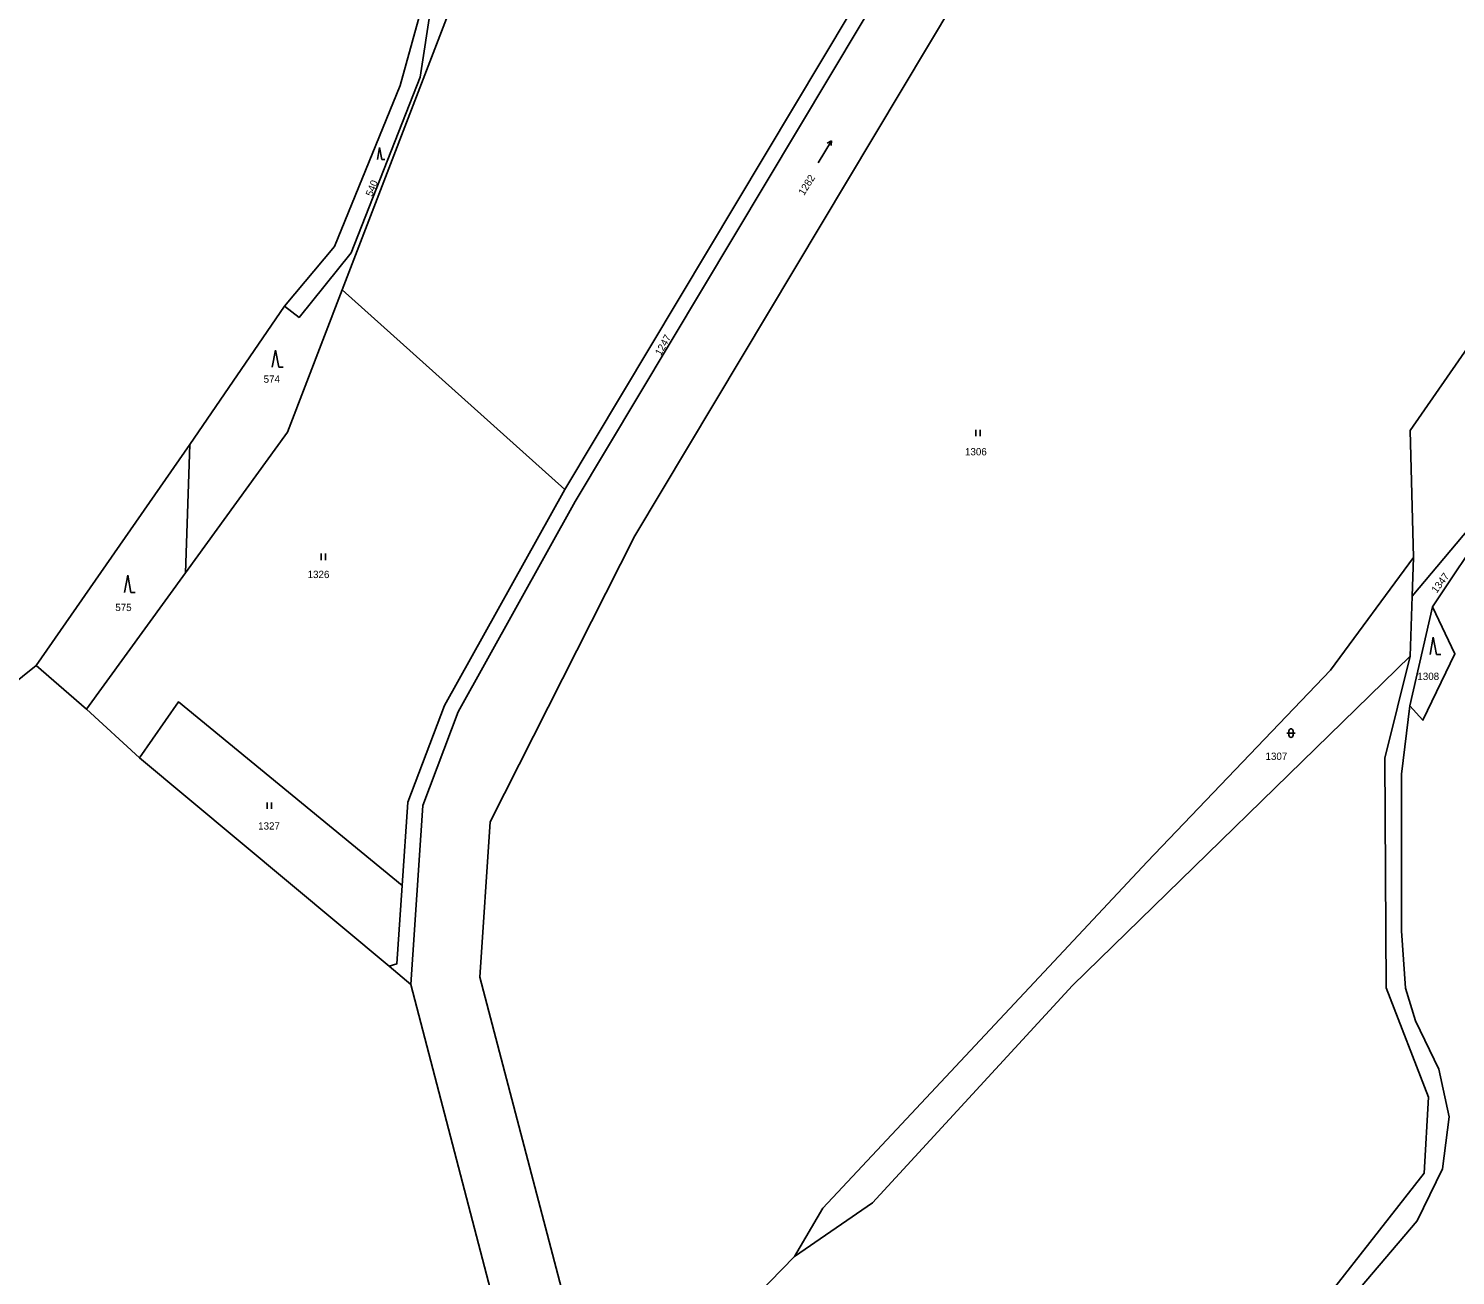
# Model space of a CAD drawing. Extents: x -520431 to -517205, y -1075927 to -1074013.
# Drawn here: x -519035.6 to -518704.2, y -1075237.3 to -1074947.7 of the extents above; entities that cross this region are included whole.
import ezdxf

# ---------------------------------------------------------------- set-up
doc = ezdxf.new("R2010")
doc.units = 0
for name, color, linetype in [('Hranice parcel', 7, 'Continuous'), ('Parcelní čísla', 7, 'Continuous'), ('Značky kultur', 7, 'Continuous')]:
    doc.layers.add(name, color=color, linetype=linetype)

msp = doc.modelspace()

# ---------------------------------------------------------------- linework, layer by layer
at = {"layer": 'Hranice parcel'}
for p, q in [((-518962.74, -1075008.44), (-518930.93, -1074925.63)), ((-518975.44, -1075041.49), (-518962.74, -1075008.44)), ((-518962.74, -1075008.44), (-518911.05, -1075054.82)), ((-518976.13, -1075012.23), (-518998.11, -1075044.33)), ((-518999.14, -1075074.14), (-518975.44, -1075041.49)), ((-518998.11, -1075044.33), (-519033.87, -1075095.67)), ((-518998.11, -1075044.33), (-518999.14, -1075074.14)), ((-518713.95, -1075070.56), (-518714.23, -1075079.58)), ((-519022.11, -1075105.8), (-518999.14, -1075074.14)), ((-518709.51, -1075082), (-518714.78, -1075105)), ((-518714.67, -1075093.46), (-518714.23, -1075079.58)), ((-519133.04, -1075175.26), (-519033.87, -1075095.67)), ((-519033.87, -1075095.67), (-519022.11, -1075105.8)), ((-519022.11, -1075105.8), (-519009.81, -1075117.14)), ((-519009.81, -1075117.14), (-518951.88, -1075165.52)), ((-518951.88, -1075165.52), (-518946.79, -1075169.77)), ((-518901.9, -1075278.15), (-518857.7, -1075232.93))]:
    msp.add_line(p, q, dxfattribs=at)
for points in [[(-518946.79, -1075169.77), (-518944.06, -1075128.15), (-518935.78, -1075106.4), (-518908.62, -1075057.57), (-518834.69, -1074934.01), (-518824.95, -1074899.48), (-518805.64, -1074797.52), (-518786.32, -1074695.57), (-518763.04, -1074636.89)], [(-518789.7, -1074694.59), (-518809.03, -1074796.64), (-518828.36, -1074898.68), (-518837.93, -1074932.61), (-518911.05, -1075054.82)], [(-518939.57, -1074925.63), (-518949.29, -1074960.98), (-518964.53, -1074998.36), (-518976.13, -1075012.23)], [(-518976.13, -1075012.23), (-518972.78, -1075014.82), (-518960.7, -1074999.79), (-518944.68, -1074959.01), (-518939.57, -1074925.63)], [(-518901.9, -1075278.15), (-518930.75, -1075168.04), (-518928.38, -1075131.95), (-518894.76, -1075065.57), (-518820.43, -1074941.35)], [(-518714.23, -1075079.58), (-518699.53, -1075062.06), (-518666.95, -1075009.26), (-518658.75, -1075000.75), (-518645.56, -1074990.66), (-518635.26, -1074977.97)], [(-518602.64, -1074986.93), (-518629.6, -1074978.08), (-518634.38, -1074980.83), (-518643.01, -1074992.79), (-518664.74, -1075011.55), (-518696.55, -1075062.68), (-518709.51, -1075082)], [(-518662.91, -1074983.55), (-518700.12, -1075020.1), (-518714.7, -1075041.05), (-518713.95, -1075070.56)], [(-518911.05, -1075054.82), (-518938.96, -1075104.92), (-518947.52, -1075127.4), (-518948.82, -1075146.77)], [(-518857.7, -1075232.93), (-518851.14, -1075221.67), (-518775.78, -1075141.24), (-518733.17, -1075096.78), (-518713.95, -1075070.56)], [(-518714.78, -1075105), (-518711.74, -1075108.38), (-518704.31, -1075092.99), (-518709.51, -1075082)], [(-518857.7, -1075232.93), (-518839.57, -1075220.45), (-518793.11, -1075170.01), (-518714.67, -1075093.46)], [(-518714.67, -1075093.46), (-518720.59, -1075117.21), (-518720.25, -1075170.49), (-518710.41, -1075195.94), (-518711.43, -1075213.58), (-518744.84, -1075256.19), (-518749.08, -1075265.49)], [(-519009.81, -1075117.14), (-519000.74, -1075104.09), (-518948.82, -1075146.77)], [(-518714.78, -1075105), (-518716.71, -1075120.9), (-518716.68, -1075157.26), (-518715.81, -1075170.58), (-518713.49, -1075178.16), (-518708.07, -1075189.38), (-518705.65, -1075200.49), (-518707.18, -1075212.55), (-518713.04, -1075224.65), (-518743.98, -1075260.99), (-518744.06, -1075268.07), (-518741.35, -1075274.68)], [(-518948.82, -1075146.77), (-518950.04, -1075164.94), (-518951.88, -1075165.52)], [(-518946.79, -1075169.77), (-518917.22, -1075283.1), (-519044.84, -1075427.3)]]:
    msp.add_lwpolyline(points, dxfattribs=at)
at = {"layer": 'Značky kultur'}
for p, q in [((-518954.06, -1074975.34), (-518954.59, -1074978.14)), ((-518953.54, -1074978.14), (-518954.06, -1074975.34)), ((-518852.23, -1074978.92), (-518849.14, -1074973.78)), ((-518849.14, -1074973.78), (-518850.07, -1074974.36)), ((-518849.14, -1074973.78), (-518849.21, -1074974.87)), ((-518953.54, -1074978.14), (-518952.84, -1074978.14)), ((-518978.25, -1075022.39), (-518979, -1075026.39)), ((-518977.5, -1075026.39), (-518978.25, -1075022.39)), ((-518977.5, -1075026.39), (-518976.5, -1075026.39)), ((-518815.57, -1075042.42), (-518815.57, -1075040.92)), ((-518814.57, -1075042.42), (-518814.57, -1075040.92)), ((-518967.61, -1075071.17), (-518967.61, -1075069.67)), ((-518966.61, -1075071.17), (-518966.61, -1075069.67)), ((-519012.57, -1075074.71), (-519013.32, -1075078.71)), ((-519011.82, -1075078.71), (-519012.57, -1075074.71)), ((-519011.82, -1075078.71), (-519010.82, -1075078.71)), ((-518709.32, -1075089.09), (-518710.07, -1075093.09)), ((-518708.57, -1075093.09), (-518709.32, -1075089.09)), ((-518708.57, -1075093.09), (-518707.57, -1075093.09)), ((-518743.37, -1075111.37), (-518741.37, -1075111.37)), ((-518742.87, -1075110.87), (-518742.87, -1075111.87)), ((-518741.87, -1075111.87), (-518741.87, -1075110.87)), ((-518980.21, -1075128.97), (-518980.21, -1075127.47)), ((-518979.21, -1075128.97), (-518979.21, -1075127.47))]:
    msp.add_line(p, q, dxfattribs=at)
for centre, start, end in [((-518742.37, -1075110.87), 0, 180), ((-518742.37, -1075111.87), 180, 359.9879)]:
    msp.add_arc(centre, 0.5, start, end, dxfattribs=at)

# ---------------------------------------------------------------- texts
at = {"layer": 'Parcelní čísla'}
for s, rotation, p in [('1282', 58, (-518855.49, -1074986.63)), ('540', 68, (-518955.81, -1074986.88)), ('1247', 61, (-518888.73, -1075023.84)), ('1347', 53, (-518708.55, -1075079.01))]:
    msp.add_text(s, height=1.7, rotation=rotation, dxfattribs=at).set_placement(p)
for s, p in [('574', (-518981.01, -1075029.99)), ('1306', (-518818.09, -1075046.86)), ('1326', (-518970.79, -1075075.36)), ('575', (-519015.46, -1075083.02)), ('1308', (-518713.02, -1075099.03)), ('1307', (-518748.29, -1075117.59)), ('1327', (-518982.28, -1075133.78))]:
    msp.add_text(s, height=1.7, dxfattribs=at).set_placement(p)

doc.saveas('drawing.dxf')
